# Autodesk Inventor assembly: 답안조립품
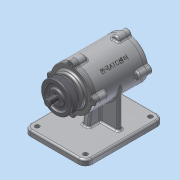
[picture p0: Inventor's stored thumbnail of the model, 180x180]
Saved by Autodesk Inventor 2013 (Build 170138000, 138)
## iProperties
Created: 2015-12
Part Number: 답안조립품
Document SubType Name: Assembly
Designer: ST1
Author: ST1
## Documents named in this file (10)
- C:\Users\ST1\Desktop\451207V1013\답안조립품.iam
- C:\Users\ST1\Desktop\451207V1013\1-본체.ipt
- C:\Users\ST1\Desktop\451207V1013\커버.ipt
- C:\Users\ST1\Desktop\451207V1013\커버2.ipt
- C:\Users\ST1\Desktop\451207V1013\축.ipt
- C:\Users\ST1\Desktop\451207V1013\키(4 x 4 x 12).ipt
- C:\Users\ST1\Desktop\451207V1013\베어링 6204.ipt
- C:\Users\ST1\Desktop\451207V1013\오일실.ipt
- C:\Users\ST1\Desktop\451207V1013\볼트 M4 x 12.ipt
- C:\Users\ST1\Desktop\451207V1013\V-벨트풀리.ipt
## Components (6 placed, 5 different names)
1. 1-본체:1 — 각도:2
2. KS B 1311 (I) 4 x 4 x 12:1 — 각도:1, 각도:2, 각도:3
3. KS B 2023 6204 - 20 x 47 x 14:1
4. KS B 2023 6204 - 20 x 47 x 14:2
5. KS B 2804 D D - 20 32 8:1 — 플러쉬:1
6. V-벨트풀리:1 — 각도:3
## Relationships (4: Angle 3, Flush 1)
- 각도:1 [Angle]: KS B 1311 (I) 4 x 4 x 12:1
- 각도:2 [Angle]: 1-본체:1 ↔ KS B 1311 (I) 4 x 4 x 12:1
- 플러쉬:1 [Flush]: KS B 2804 D D - 20 32 8:1
- 각도:3 [Angle]: KS B 1311 (I) 4 x 4 x 12:1 ↔ V-벨트풀리:1
